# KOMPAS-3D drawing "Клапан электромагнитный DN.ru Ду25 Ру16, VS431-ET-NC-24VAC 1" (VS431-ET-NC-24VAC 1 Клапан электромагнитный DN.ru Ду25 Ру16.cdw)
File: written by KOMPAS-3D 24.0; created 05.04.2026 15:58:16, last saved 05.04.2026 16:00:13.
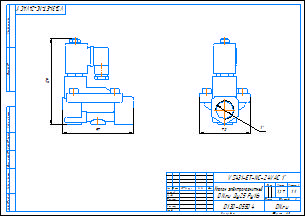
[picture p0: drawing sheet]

Document properties: c3d_UniqueCompID: ef56311e-7521-43dc-8291-0e6108b3d81d; Автор: artio; Класс точности: c; Знак неуказанной шероховатости: Шероховатость не задана; Рассекать на разрезах: Да; c3d_UniqueCompID: ef56311e-7521-43dc-8291-0e6108b3d81d; Автор: artio; Класс точности: c; Знак неуказанной шероховатости: Шероховатость не задана; Рассекать на разрезах: Да; Автор: artio; Форматы листов документа: A3; Полное имя файла: VS431-ET-NC-24VAC 1 Клапан электромагнитный DN.ru Ду25 Ру16.m3d; Масса: 1.267; Наименование: Клапан электромагнитный DN.ru Ду25 Ру16; Количество листов документа: 1; Примечание: D130-05504

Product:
- Body: Тело 1  | qty 1
    Масса: 1.729172
- Part/product: Клапан электромагнитный DN.ru Ду25 Ру16  | designation VS431-ET-NC-24VAC 1
    Масса: 1.267
    Раздел спецификации: Прочие изделия
    Примечание: D130-05504
    additional columns: ef56311e-7521-43dc-8291-0e6108b3d81d; artio; c; Шероховатость не задана; Да

Views: Вид 1, Спереди, Проекционный вид 2
Referenced files in C:\Users\artio\OneDrive\Рабочий стол\Клапан электромагнитный DN.ru\VS431\VS431-ET-NC\: VS431-ET-NC-24VAC 3-4 Клапан электромагнитный DN.ru Ду20 Ру16.m3d, VS431-ET-NC-24VAC 1 Клапан электромагнитный DN.ru Ду25 Ру16.m3d, VS431-ET-NC-24VAC 3-4 Клапан электромагнитный DN.ru Ду20 Ру16.cdw
Referenced files in C:\Users\artio\OneDrive\Рабочий стол\Клапан электромагнитный DN.ru\VS431\VS431-ET-NC\VS431-ET-NC-24VAC\Ду25\: VS431-ET-NC-24VAC 1 Клапан электромагнитный DN.ru Ду25 Ру16.m3d
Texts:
  VS431-ET-NC-24VAC 1
  Клапан электромагнитный
  DN.ru Ду25 Ру16
  VS431-ET-NC-24VAC 1"
  VS431-ET-NC-24VAC 1"-
  Клапан электромагнитный DN.ru Ду25 Ру16
  VS431-ET-NC-24VAC 1 Клапан электромагнитный DN.ru Ду25 Ру16
Dimensions and other numbers on the sheet: 0; 3; 2; 4; 70; 97; 119; 1:1; 1; 1,27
